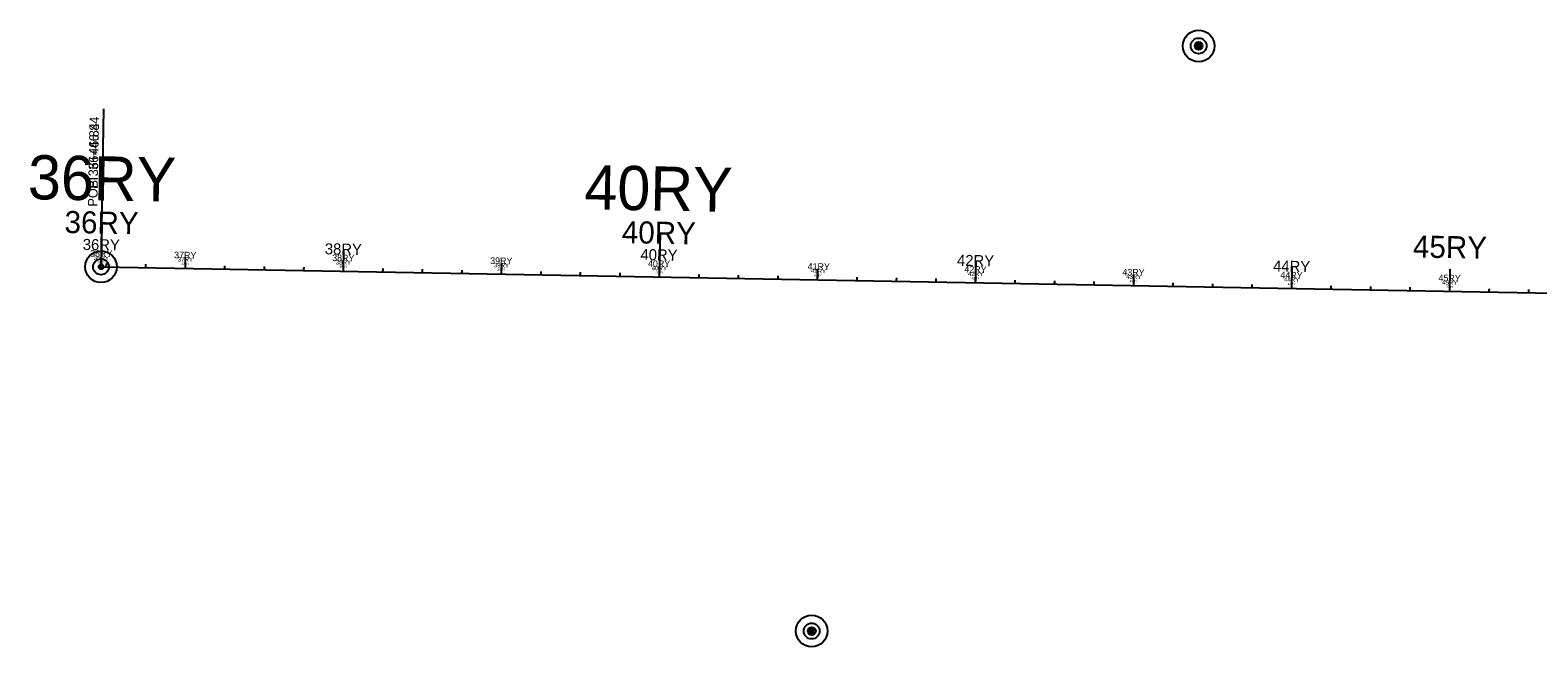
# Model space of a CAD drawing. Extents: x 564646 to 607088, y 225853 to 261760.
# Drawn here: x 597131 to 598085, y 238813 to 239204 of the extents above; entities that cross this region are included whole.
import ezdxf

# ---------------------------------------------------------------- set-up
doc = ezdxf.new("R2010")
doc.units = 0
for name, color, linetype in [('B_CONC_HIDDEN_LT', 7, 'Continuous'), ('B_CONST', 7, 'Continuous'), ('B_EXIST', 7, 'Continuous'), ('B_TEXT', 7, 'Continuous'), ('E-Easements', 7, 'Continuous'), ('E-Property Lines', 7, 'Continuous'), ('E_ALI_100', 7, 'Continuous'), ('E_RW_CorporateLimits', 7, 'Continuous'), ('E_RW_EasementUtility_Text', 7, 'Continuous'), ('E_WTR_FlowLine', 7, 'Continuous'), ('EMCS_SURVEY_PT CODES', 7, 'Continuous'), ('EMCS_SURVEY_PT ELEV', 7, 'Continuous'), ('EMCS_SURVEY_PT NOTES', 7, 'Continuous'), ('Level 33', 7, 'Continuous'), ('P-Easements Floodplain', 7, 'Continuous'), ('P-Easements Temporary', 7, 'Continuous'), ('P_ALI_100_Tic', 7, 'Continuous'), ('P_ALI_20', 7, 'Continuous'), ('P_ALI_50', 7, 'Continuous'), ('P_RW_AccessPreviousProject Txt', 7, 'Continuous'), ('P_RW_EasementPerm', 7, 'Continuous'), ('P_RW_PropertyConnector', 7, 'Continuous'), ('P_RW_Proposed', 7, 'Continuous'), ('P_WAL', 7, 'Continuous')]:
    doc.layers.add(name, color=color, linetype=linetype)

msp = doc.modelspace()

# ---------------------------------------------------------------- linework, layer by layer
at = {"layer": 'B_CONC_HIDDEN_LT'}
msp.add_line((597176.17, 239053.94), (599834.96, 239005.61), dxfattribs=at)
at = {"layer": 'B_CONST'}
for centre in [(597870.53, 239193.8), (597870.53, 239193.8), (597176.17, 239053.94), (597176.17, 239053.94), (597625.76, 238823.32), (597625.76, 238823.32)]:
    msp.add_circle(centre, 1.5, dxfattribs=at)
at = {"layer": 'B_EXIST'}
for centre in [(597870.53, 239193.8), (597176.17, 239053.94), (597625.76, 238823.32)]:
    msp.add_circle(centre, 5, dxfattribs=at)
at = {"layer": 'B_TEXT'}
msp.add_lwpolyline([(597176.17, 239053.94), (597177.99, 239153.92)], dxfattribs=at)
at = {"layer": 'E-Easements'}
for centre in [(597870.53, 239193.8), (597625.76, 238823.32)]:
    msp.add_circle(centre, 2.5, dxfattribs=at)
at = {"layer": 'E_ALI_100'}
for points in [[(597176.22, 239056.74), (597176.17, 239053.94)], [(597176.2, 239055.34), (597176.17, 239053.94)], [(597179.35, 239055.28), (597179.33, 239053.88)], [(597204.35, 239054.83), (597204.33, 239053.43)], [(597229.37, 239055.77), (597229.32, 239052.97)], [(597254.34, 239053.92), (597254.32, 239052.52)], [(597279.34, 239053.46), (597279.31, 239052.07)], [(597304.33, 239053.01), (597304.31, 239051.61)], [(597329.36, 239053.96), (597329.3, 239051.16)], [(597354.33, 239052.1), (597354.3, 239050.7)], [(597379.32, 239051.65), (597379.3, 239050.25)], [(597404.32, 239051.19), (597404.29, 239049.79)], [(597429.34, 239052.14), (597429.29, 239049.34)], [(597454.31, 239050.28), (597454.28, 239048.88)], [(597479.31, 239049.83), (597479.28, 239048.43)], [(597529.32, 239050.32), (597529.27, 239047.52)], [(597504.3, 239049.38), (597504.28, 239047.98)], [(597554.29, 239048.47), (597554.27, 239047.07)], [(597579.29, 239048.01), (597579.26, 239046.61)], [(597604.28, 239047.56), (597604.26, 239046.16)], [(597629.31, 239048.5), (597629.26, 239045.7)], [(597654.28, 239046.65), (597654.25, 239045.25)], [(597679.27, 239046.2), (597679.25, 239044.8)], [(597704.27, 239045.74), (597704.24, 239044.34)], [(597729.29, 239046.69), (597729.24, 239043.89)], [(597754.26, 239044.83), (597754.23, 239043.43)], [(597779.26, 239044.38), (597779.23, 239042.98)], [(597804.25, 239043.92), (597804.23, 239042.52)], [(597829.27, 239044.87), (597829.22, 239042.07)], [(597854.24, 239043.01), (597854.22, 239041.61)], [(597879.24, 239042.56), (597879.21, 239041.16)], [(597904.24, 239042.11), (597904.21, 239040.71)], [(597929.26, 239043.05), (597929.21, 239040.25)], [(597954.23, 239041.2), (597954.2, 239039.8)], [(597979.22, 239040.74), (597979.2, 239039.34)], [(598004.22, 239040.29), (598004.19, 239038.89)], [(598029.24, 239041.23), (598029.19, 239038.43)], [(598054.21, 239039.38), (598054.18, 239037.98)], [(598079.21, 239038.93), (598079.18, 239037.53)]]:
    msp.add_lwpolyline(points, dxfattribs=at)
at = {"layer": 'E_WTR_FlowLine'}
for centre in [(597870.53, 239193.8), (597176.17, 239053.94), (597625.76, 238823.32)]:
    msp.add_circle(centre, 0.5, dxfattribs=at)
at = {"layer": 'EMCS_SURVEY_PT CODES'}
msp.add_line((597176.17, 239053.94), (599834.96, 239005.61), dxfattribs=at)
at = {"layer": 'EMCS_SURVEY_PT ELEV'}
msp.add_line((597176.17, 239053.94), (599834.96, 239005.61), dxfattribs=at)
msp.add_line((597176.17, 239053.94), (599834.96, 239005.61), dxfattribs=at)
at = {"layer": 'Level 33'}
for points in [[(597176.2, 239055.34), (597176.17, 239053.94)], [(597176.18, 239054.64), (597176.17, 239053.94)], [(597179.34, 239054.58), (597179.33, 239053.88)], [(597204.34, 239054.13), (597204.33, 239053.43)], [(597229.35, 239054.37), (597229.32, 239052.97)], [(597254.33, 239053.22), (597254.32, 239052.52)], [(597279.33, 239052.77), (597279.31, 239052.07)], [(597304.32, 239052.31), (597304.31, 239051.61)], [(597329.33, 239052.56), (597329.3, 239051.16)], [(597354.31, 239051.4), (597354.3, 239050.7)], [(597379.31, 239050.95), (597379.3, 239050.25)], [(597404.31, 239050.49), (597404.29, 239049.79)], [(597429.31, 239050.74), (597429.29, 239049.34)], [(597454.3, 239049.58), (597454.28, 239048.88)], [(597479.29, 239049.13), (597479.28, 239048.43)], [(597504.29, 239048.68), (597504.28, 239047.98)], [(597529.3, 239048.92), (597529.27, 239047.52)], [(597554.28, 239047.77), (597554.27, 239047.07)], [(597579.28, 239047.31), (597579.26, 239046.61)], [(597604.27, 239046.86), (597604.26, 239046.16)], [(597629.28, 239047.1), (597629.26, 239045.7)], [(597654.26, 239045.95), (597654.25, 239045.25)], [(597679.26, 239045.5), (597679.25, 239044.8)], [(597704.26, 239045.04), (597704.24, 239044.34)], [(597729.26, 239045.29), (597729.24, 239043.89)], [(597754.25, 239044.13), (597754.23, 239043.43)], [(597779.24, 239043.68), (597779.23, 239042.98)], [(597804.24, 239043.22), (597804.23, 239042.52)], [(597829.25, 239043.47), (597829.22, 239042.07)], [(597854.23, 239042.31), (597854.22, 239041.61)], [(597879.23, 239041.86), (597879.21, 239041.16)], [(597904.22, 239041.41), (597904.21, 239040.71)], [(597929.23, 239041.65), (597929.21, 239040.25)], [(597954.21, 239040.5), (597954.2, 239039.8)], [(597979.21, 239040.04), (597979.2, 239039.34)], [(598004.21, 239039.59), (598004.19, 239038.89)], [(598029.21, 239039.83), (598029.19, 239038.43)], [(598054.2, 239038.68), (598054.18, 239037.98)], [(598079.19, 239038.23), (598079.18, 239037.53)]]:
    msp.add_lwpolyline(points, dxfattribs=at)
at = {"layer": 'P-Easements Floodplain'}
msp.add_line((597176.17, 239053.94), (599834.96, 239005.61), dxfattribs=at)
at = {"layer": 'P-Easements Temporary'}
for centre in [(597870.53, 239193.8), (597176.17, 239053.94), (597625.76, 238823.32)]:
    msp.add_circle(centre, 10, dxfattribs=at)
at = {"layer": 'P_ALI_100_Tic'}
for points in [[(597176.68, 239081.94), (597176.17, 239053.94)], [(597529.78, 239075.52), (597529.27, 239047.52)], [(597176.42, 239067.94), (597176.17, 239053.94)], [(597329.56, 239065.15), (597329.3, 239051.16)], [(597729.49, 239057.88), (597729.24, 239043.89)], [(597929.46, 239054.25), (597929.21, 239040.25)]]:
    msp.add_lwpolyline(points, dxfattribs=at)
at = {"layer": 'P_ALI_20'}
for points in [[(597176.42, 239067.94), (597176.17, 239053.94)], [(597176.3, 239060.94), (597176.17, 239053.94)], [(597229.45, 239059.97), (597229.32, 239052.97)], [(597529.53, 239061.52), (597529.27, 239047.52)], [(597329.43, 239058.16), (597329.3, 239051.16)], [(597429.42, 239056.34), (597429.29, 239049.34)], [(597629.38, 239052.7), (597629.26, 239045.7)], [(597729.37, 239050.89), (597729.24, 239043.89)], [(598029.44, 239052.43), (598029.19, 239038.43)], [(597829.35, 239049.07), (597829.22, 239042.07)], [(597929.33, 239047.25), (597929.21, 239040.25)]]:
    msp.add_lwpolyline(points, dxfattribs=at)
at = {"layer": 'P_ALI_50'}
msp.add_lwpolyline([(597176.17, 239053.94), (597177.99, 239153.92)], dxfattribs=at)
at = {"layer": 'P_RW_AccessPreviousProject Txt'}
for points in [[(597176.25, 239058.14), (597176.17, 239053.94)], [(597176.21, 239056.04), (597176.17, 239053.94)], [(597179.37, 239055.98), (597179.33, 239053.88)], [(597204.36, 239055.53), (597204.33, 239053.43)], [(597229.4, 239057.17), (597229.32, 239052.97)], [(597254.36, 239054.62), (597254.32, 239052.52)], [(597279.35, 239054.16), (597279.31, 239052.07)], [(597304.35, 239053.71), (597304.31, 239051.61)], [(597329.38, 239055.36), (597329.3, 239051.16)], [(597354.34, 239052.8), (597354.3, 239050.7)], [(597379.33, 239052.35), (597379.3, 239050.25)], [(597404.33, 239051.89), (597404.29, 239049.79)], [(597429.36, 239053.54), (597429.29, 239049.34)], [(597454.32, 239050.98), (597454.28, 239048.88)], [(597479.32, 239050.53), (597479.28, 239048.43)], [(597504.31, 239050.08), (597504.28, 239047.98)], [(597529.35, 239051.72), (597529.27, 239047.52)], [(597629.33, 239049.9), (597629.26, 239045.7)], [(597554.31, 239049.17), (597554.27, 239047.07)], [(597579.3, 239048.71), (597579.26, 239046.61)], [(597604.3, 239048.26), (597604.26, 239046.16)], [(597654.29, 239047.35), (597654.25, 239045.25)], [(597679.29, 239046.9), (597679.25, 239044.8)], [(597704.28, 239046.44), (597704.24, 239044.34)], [(597729.31, 239048.09), (597729.24, 239043.89)], [(597754.27, 239045.53), (597754.23, 239043.43)], [(597779.27, 239045.08), (597779.23, 239042.98)], [(597804.26, 239044.62), (597804.23, 239042.52)], [(597829.3, 239046.27), (597829.22, 239042.07)], [(597854.26, 239043.71), (597854.22, 239041.61)], [(597879.25, 239043.26), (597879.21, 239041.16)], [(597904.25, 239042.81), (597904.21, 239040.71)], [(597929.28, 239044.45), (597929.21, 239040.25)], [(597954.24, 239041.9), (597954.2, 239039.8)], [(597979.24, 239041.44), (597979.2, 239039.34)], [(598004.23, 239040.99), (598004.19, 239038.89)], [(598029.27, 239042.63), (598029.19, 239038.43)], [(598054.22, 239040.08), (598054.18, 239037.98)], [(598079.22, 239039.63), (598079.18, 239037.53)]]:
    msp.add_lwpolyline(points, dxfattribs=at)
at = {"layer": 'P_RW_EasementPerm'}
for points in [[(597176.3, 239060.94), (597176.17, 239053.94)], [(597176.23, 239057.44), (597176.17, 239053.94)], [(597229.38, 239056.47), (597229.32, 239052.97)], [(597329.43, 239058.16), (597329.3, 239051.16)], [(597429.35, 239052.84), (597429.29, 239049.34)], [(597529.4, 239054.52), (597529.27, 239047.52)], [(597729.37, 239050.89), (597729.24, 239043.89)], [(597629.32, 239049.2), (597629.26, 239045.7)], [(597829.29, 239045.57), (597829.22, 239042.07)], [(597929.33, 239047.25), (597929.21, 239040.25)], [(598029.25, 239041.93), (598029.19, 239038.43)]]:
    msp.add_lwpolyline(points, dxfattribs=at)
at = {"layer": 'P_RW_PropertyConnector'}
msp.add_line((597176.17, 239053.94), (599834.96, 239005.61), dxfattribs=at)
at = {"layer": 'P_WAL'}
for centre in [(597870.53, 239193.8), (597176.17, 239053.94), (597625.76, 238823.32)]:
    msp.add_circle(centre, 1, dxfattribs=at)

# ---------------------------------------------------------------- texts
for s, p in [('36RY', (597171.53, 239058.23)), ('37RY', (597224.68, 239057.26)), ('38RY', (597324.66, 239055.44)), ('39RY', (597424.63, 239053.62)), ('40RY', (597524.52, 239051.81)), ('41RY', (597625.19, 239049.98)), ('42RY', (597724.6, 239048.17)), ('43RY', (597824.58, 239046.35)), ('44RY', (597924.56, 239044.54)), ('45RY', (598024.55, 239042.72))]:
    msp.add_text(s, height=2.8, rotation=358.95862).set_placement(p)
at = {"layer": 'B_TEXT'}
msp.add_text('POB 36+46.84', height=6, rotation=88.95862, dxfattribs=at).set_placement((597173.86, 239092.01))
at = {"layer": 'E-Property Lines'}
for s, p in [('36RY', (597129.76, 239096.79)), ('40RY', (597481.76, 239090.39))]:
    msp.add_text(s, height=28, rotation=358.95862, dxfattribs=at).set_placement(p)
at = {"layer": 'E_RW_CorporateLimits'}
for s, p in [('36RY', (597152.97, 239075.37)), ('40RY', (597505.52, 239068.96)), ('45RY', (598005.99, 239059.86))]:
    msp.add_text(s, height=14, rotation=358.95862, dxfattribs=at).set_placement(p)
at = {"layer": 'E_RW_EasementUtility_Text'}
for s, p in [('36RY', (597173.85, 239056.08)), ('37RY', (597227, 239055.12)), ('38RY', (597326.98, 239053.3)), ('39RY', (597426.96, 239051.48)), ('40RY', (597526.9, 239049.67)), ('41RY', (597627.22, 239047.84)), ('42RY', (597726.92, 239046.03)), ('43RY', (597826.9, 239044.21)), ('44RY', (597926.89, 239042.39)), ('45RY', (598026.87, 239040.58))]:
    msp.add_text(s, height=1.4, rotation=358.95862, dxfattribs=at).set_placement(p)
at = {"layer": 'EMCS_SURVEY_PT NOTES'}
for s, p in [('36RY', (597169.21, 239060.37)), ('37RY', (597222.36, 239059.4)), ('38RY', (597322.34, 239057.58)), ('39RY', (597422.29, 239055.77)), ('40RY', (597522.15, 239053.95)), ('41RY', (597623.15, 239052.12)), ('42RY', (597722.28, 239050.31)), ('43RY', (597822.26, 239048.5)), ('44RY', (597922.24, 239046.68)), ('45RY', (598022.23, 239044.86))]:
    msp.add_text(s, height=4.2, rotation=358.95862, dxfattribs=at).set_placement(p)
at = {"layer": 'P_ALI_50'}
msp.add_text('PI  36+46.84', height=6, rotation=88.95862, dxfattribs=at).set_placement((597174.07, 239103.25))
at = {"layer": 'P_RW_Proposed'}
for s, p in [('36RY', (597164.57, 239064.65)), ('38RY', (597317.7, 239061.87)), ('40RY', (597517.39, 239058.24)), ('42RY', (597717.64, 239054.6)), ('44RY', (597917.6, 239050.96))]:
    msp.add_text(s, height=7, rotation=358.95862, dxfattribs=at).set_placement(p)

doc.saveas('drawing.dxf')
